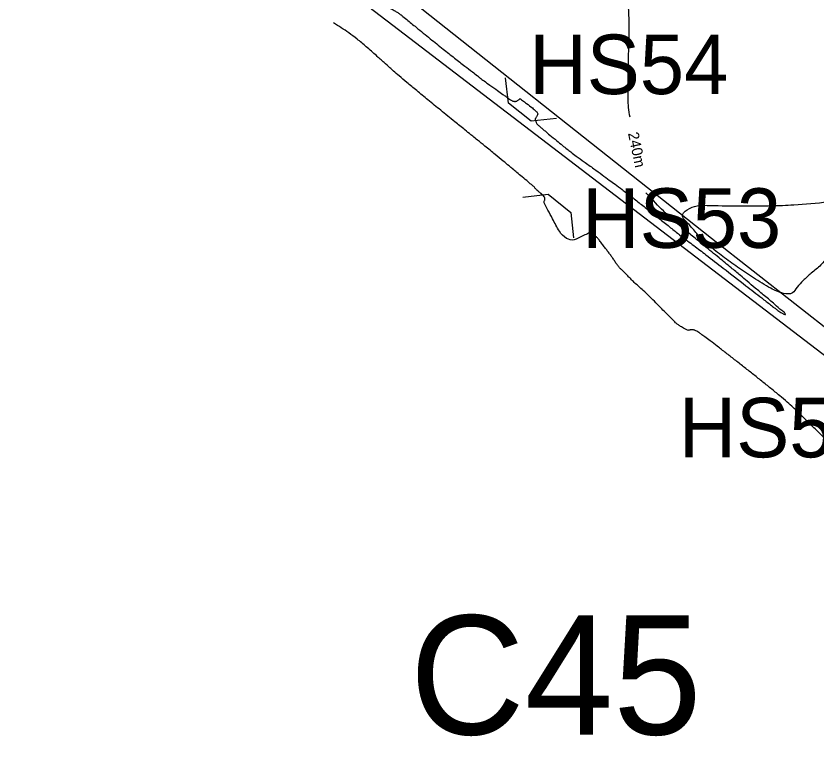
# Model space of a CAD drawing. Extents: x -478495 to -472450, y -1118050 to -1113745.
# Drawn here: x -476976.4 to -476841.8, y -1115248.8 to -1115126.7 of the extents above; entities that cross this region are included whole.
import ezdxf

# ---------------------------------------------------------------- set-up
doc = ezdxf.new("R2010")
doc.units = 0
for name, color, linetype in [('cesty', 7, 'Continuous'), ('cyklostezka', 7, 'Continuous'), ('hospodářské sjezdy', 7, 'Continuous'), ('silnice', 7, 'Continuous'), ('Vrstevnice_hlavni', 7, 'Continuous'), ('Vrstevnice_popis', 7, 'Continuous'), ('Vrstevnice_vedlejsi', 7, 'Continuous')]:
    doc.layers.add(name, color=color, linetype=linetype)

msp = doc.modelspace()

# ---------------------------------------------------------------- linework, layer by layer
at = {"layer": 'cyklostezka'}
msp.add_lwpolyline([(-477033.5754190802, -1115019.3150603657), (-476978.4562666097, -1115069.8432601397), (-476859.56050309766, -1115163.970078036), (-476838.56618741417, -1115180.4272610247), (-476823.49769734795, -1115192.2844335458), (-476742.0352354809, -1115258.9995421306), (-476654.0177406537, -1115335.224940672), (-476615.8651919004, -1115370.6739552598), (-476567.0504242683, -1115426.523456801)], dxfattribs=at)
at = {"layer": 'hospodářské sjezdy'}
for p, q in [((-476893.6856083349, -1115141.2997878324), (-476894.1564470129, -1115137.060401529)), ((-476889.873, -1115144.354), (-476893.6856083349, -1115141.2997878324)), ((-476885.6330406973, -1115143.888349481), (-476889.873, -1115144.354)), ((-476891.2552469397, -1115157.0783249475), (-476887.015287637, -1115156.6126744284)), ((-476887.015287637, -1115156.6126744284), (-476883.2026793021, -1115159.666886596)), ((-476883.2026793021, -1115159.666886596), (-476882.7318406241, -1115163.9062728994))]:
    msp.add_line(p, q, dxfattribs=at)
at = {"layer": 'silnice'}
msp.add_lwpolyline([(-476200.5430969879, -1116268.1533225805), (-476239.9646638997, -1116179.1988064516), (-476260.9335824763, -1116109.5457419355), (-476288.6125549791, -1116007.1641290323), (-476289.4513117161, -1115970.2396129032), (-476274.35369035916, -1115930.797516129), (-476257.5785554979, -1115904.782516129), (-476369.13277385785, -1115816.6670000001), (-476386.7466654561, -1115803.239903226), (-476421.13569191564, -1115718.4813548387), (-476492.4300150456, -1115557.3561935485), (-476531.85169606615, -1115480.150387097), (-476576.30580343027, -1115421.4068387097), (-476632.5025051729, -1115358.4673225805), (-476738.18585476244, -1115266.156032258), (-476821.72644138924, -1115198.097580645), (-476986.4582147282, -1115072.218548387), (-477038.7966192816, -1115021.8669354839), (-477039.4315830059, -1115021.0219319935)], dxfattribs=at)
at = {"layer": 'Vrstevnice_hlavni'}
for points in [[(-476873.251, -1115143.677), (-476873.507, -1115142.01), (-476873.554, -1115139.102), (-476873.522, -1115134.12), (-476873.41000000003, -1115127.063), (-476873.808, -1115122.0860000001), (-476874.717, -1115119.19), (-476876.136, -1115118.374), (-476877.354, -1115117.171), (-476878.371, -1115115.579), (-476879.185, -1115113.6), (-476882.364, -1115111.475), (-476887.908, -1115109.205), (-476895.815, -1115106.789), (-476902.242, -1115103.761), (-476907.186, -1115100.12), (-476910.64900000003, -1115095.867), (-476913.66000000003, -1115091.883), (-476916.218, -1115088.1670000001), (-476918.324, -1115084.72), (-476919.72500000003, -1115082.379), (-476920.42100000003, -1115081.145), (-476920.412, -1115081.017), (-476920.42600000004, -1115080.932), (-476920.462, -1115080.891), (-476920.521, -1115080.893), (-476920.576, -1115080.895), (-476920.62700000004, -1115080.896), (-476920.674, -1115080.898), (-476921.73600000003, -1115080.799), (-476923.814, -1115080.599), (-476926.907, -1115080.3), (-476932.302, -1115079.591), (-476940, -1115078.472), (-476950, -1115076.9440000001), (-476957.876, -1115075.006), (-476963.629, -1115072.6570000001), (-476967.259, -1115069.897), (-476970.802, -1115067.892), (-476974.259, -1115066.643), (-476977.631, -1115066.149), (-476980.601, -1115065.341), (-476983.17, -1115064.218), (-476985.338, -1115062.781), (-476986.878, -1115061.747), (-476987.79000000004, -1115061.118), (-476988.074, -1115060.892), (-476988.478, -1115060.587), (-476989.003, -1115060.204), (-476989.648, -1115059.743), (-476990.332, -1115059.246), (-476991.055, -1115058.714), (-476991.817, -1115058.146), (-476992.891, -1115057.395), (-476994.277, -1115056.46), (-476995.976, -1115055.343), (-476997.039, -1115054.593), (-476997.46400000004, -1115054.21), (-476997.254, -1115054.195), (-476998.009, -1115053.437), (-476999.729, -1115051.937), (-477002.416, -1115049.693), (-477004.444, -1115048.001), (-477005.814, -1115046.86), (-477006.527, -1115046.27), (-477007.324, -1115045.723), (-477008.206, -1115045.2210000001), (-477009.173, -1115044.763), (-477009.833, -1115044.445), (-477010.186, -1115044.267), (-477010.232, -1115044.2280000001), (-477010.318, -1115044.158), (-477010.443, -1115044.058), (-477010.608, -1115043.927), (-477010.86600000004, -1115043.703), (-477011.219, -1115043.389), (-477011.666, -1115042.982), (-477011.859, -1115042.654), (-477011.79600000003, -1115042.405), (-477011.479, -1115042.235), (-477011.695, -1115041.8460000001), (-477012.445, -1115041.236), (-477013.729, -1115040.4070000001), (-477014.642, -1115039.799), (-477015.184, -1115039.41), (-477015.355, -1115039.241), (-477015.476, -1115039.117), (-477015.545, -1115039.038), (-477015.564, -1115039.003), (-477015.672, -1115038.875), (-477015.869, -1115038.653), (-477016.157, -1115038.339), (-477016.405, -1115038.07), (-477016.615, -1115037.849), (-477016.786, -1115037.674), (-477017.213, -1115037.2820000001), (-477017.89400000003, -1115036.673)], [(-476935.331, -1115108.3190000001), (-476934.947, -1115108.607), (-476934.41500000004, -1115109.009), (-476933.73600000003, -1115109.525), (-476932.909, -1115110.156), (-476932.006, -1115110.842), (-476931.026, -1115111.583), (-476929.968, -1115112.379), (-476928.913, -1115113.236), (-476927.86, -1115114.154), (-476926.808, -1115115.132), (-476926.037, -1115115.767), (-476925.54600000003, -1115116.058), (-476925.335, -1115116.006), (-476925.325, -1115115.864), (-476925.515, -1115115.632), (-476925.905, -1115115.311), (-476926.044, -1115115.192), (-476925.931, -1115115.276), (-476925.565, -1115115.563), (-476925.29000000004, -1115115.779), (-476925.105, -1115115.925), (-476925.01, -1115116.002), (-476924.95, -1115116.053), (-476924.925, -1115116.079), (-476924.935, -1115116.079), (-476924.936, -1115116.133), (-476924.927, -1115116.239), (-476924.909, -1115116.398), (-476924.628, -1115116.734), (-476924.083, -1115117.247), (-476923.275, -1115117.937), (-476921.987, -1115119.01), (-476920.22000000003, -1115120.464), (-476917.972, -1115122.302), (-476916.102, -1115123.736), (-476914.608, -1115124.768), (-476913.49, -1115125.397), (-476912.67600000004, -1115125.868), (-476912.164, -1115126.18), (-476911.956, -1115126.335), (-476911.795, -1115126.454), (-476911.684, -1115126.538), (-476911.62, -1115126.587), (-476910.788, -1115127.262), (-476909.18700000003, -1115128.562), (-476906.818, -1115130.4880000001), (-476904.666, -1115132.215), (-476902.733, -1115133.742), (-476901.01900000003, -1115135.07), (-476899.74, -1115136.063), (-476898.897, -1115136.7210000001), (-476898.49, -1115137.044), (-476897.79000000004, -1115137.566), (-476896.79600000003, -1115138.286), (-476895.509, -1115139.205), (-476894.623, -1115139.837), (-476894.139, -1115140.183), (-476894.056, -1115140.242), (-476893.9, -1115140.355), (-476893.67, -1115140.521), (-476893.367, -1115140.74), (-476893.126, -1115140.887), (-476892.94800000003, -1115140.962), (-476892.83400000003, -1115140.965), (-476892.748, -1115140.977), (-476892.691, -1115140.997), (-476892.664, -1115141.027), (-476892.601, -1115141.034), (-476892.501, -1115141.018), (-476892.364, -1115140.98), (-476892.219, -1115140.91), (-476892.065, -1115140.81), (-476891.902, -1115140.679), (-476891.793, -1115140.591), (-476891.738, -1115140.546), (-476891.737, -1115140.543), (-476891.726, -1115140.55), (-476891.70300000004, -1115140.565), (-476891.67100000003, -1115140.589), (-476891.32, -1115140.854), (-476890.651, -1115141.361), (-476889.664, -1115142.109), (-476889.038, -1115142.693), (-476888.773, -1115143.114), (-476888.869, -1115143.371), (-476888.96400000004, -1115143.585), (-476889.059, -1115143.757), (-476889.15400000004, -1115143.887), (-476889.202, -1115143.9980000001), (-476889.202, -1115144.091), (-476889.15400000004, -1115144.166), (-476889.109, -1115144.273), (-476889.066, -1115144.412), (-476889.025, -1115144.583), (-476888.922, -1115144.761), (-476888.756, -1115144.947)], [(-476909.112, -1115139.205), (-476910.765, -1115137.833), (-476912.065, -1115136.734), (-476913.014, -1115135.91), (-476913.61, -1115135.36), (-476914.568, -1115134.496), (-476915.89, -1115133.318), (-476917.57300000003, -1115131.827), (-476919.12, -1115130.555), (-476920.52900000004, -1115129.502), (-476923.072, -1115127.835)], [(-476845.099, -1115193.1300000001), (-476845.83900000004, -1115192.41), (-476846.835, -1115191.519), (-476848.08900000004, -1115190.457), (-476849.601, -1115189.225), (-476851.12, -1115188), (-476852.648, -1115186.783), (-476854.184, -1115185.575), (-476855.685, -1115184.401), (-476857.152, -1115183.259), (-476858.58400000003, -1115182.151), (-476859.759, -1115181.253), (-476860.677, -1115180.563), (-476861.33900000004, -1115180.083), (-476861.843, -1115179.7380000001), (-476862.19, -1115179.528), (-476862.38, -1115179.453), (-476862.58400000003, -1115179.4070000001), (-476862.802, -1115179.3900000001), (-476863.033, -1115179.403), (-476863.218, -1115179.423), (-476863.357, -1115179.45), (-476863.451, -1115179.484), (-476863.713, -1115179.3900000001), (-476864.143, -1115179.1670000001), (-476864.743, -1115178.815), (-476865.227, -1115178.4880000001), (-476865.596, -1115178.186), (-476865.849, -1115177.909), (-476866.126, -1115177.624), (-476866.428, -1115177.33), (-476866.753, -1115177.028), (-476867.316, -1115176.4710000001), (-476868.117, -1115175.659), (-476869.157, -1115174.592), (-476870.123, -1115173.638), (-476871.017, -1115172.797), (-476871.836, -1115172.0690000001), (-476872.543, -1115171.4170000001), (-476873.136, -1115170.84), (-476873.615, -1115170.339), (-476874.055, -1115169.892), (-476874.455, -1115169.501), (-476874.815, -1115169.166), (-476875.17100000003, -1115168.764), (-476875.52400000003, -1115168.297), (-476875.87200000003, -1115167.764), (-476876.23, -1115167.243), (-476876.598, -1115166.734), (-476876.97500000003, -1115166.2380000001), (-476877.38, -1115165.704), (-476877.813, -1115165.134), (-476878.273, -1115164.527), (-476878.668, -1115164.05), (-476878.999, -1115163.702), (-476879.266, -1115163.485), (-476879.494, -1115163.3090000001), (-476879.683, -1115163.175), (-476879.83400000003, -1115163.084), (-476880.378, -1115163.239), (-476881.314, -1115163.642), (-476882.64400000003, -1115164.291), (-476883.912, -1115164.024), (-476885.117, -1115162.84), (-476886.261, -1115160.74), (-476887.06200000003, -1115159.257), (-476887.521, -1115158.391), (-476887.63800000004, -1115158.143), (-476887.685, -1115157.928), (-476887.662, -1115157.746), (-476887.569, -1115157.598), (-476887.54600000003, -1115157.427), (-476887.593, -1115157.234), (-476887.71, -1115157.019), (-476887.916, -1115156.772), (-476888.212, -1115156.494), (-476888.598, -1115156.185), (-476888.896, -1115155.923), (-476889.107, -1115155.707), (-476889.231, -1115155.538), (-476889.651, -1115155.146), (-476890.369, -1115154.53), (-476891.382, -1115153.692), (-476892.256, -1115152.965), (-476892.988, -1115152.35), (-476893.58, -1115151.848), (-476894.552, -1115151.0420000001), (-476895.90400000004, -1115149.9340000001), (-476897.635, -1115148.524), (-476898.89400000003, -1115147.501), (-476899.681, -1115146.865), (-476899.995, -1115146.616), (-476900.999, -1115145.806), (-476902.693, -1115144.437), (-476905.076, -1115142.507), (-476907.216, -1115140.763), (-476909.112, -1115139.205)], [(-476888.756, -1115144.947), (-476888.528, -1115145.142), (-476888.329, -1115145.312), (-476888.161, -1115145.459), (-476888.021, -1115145.583), (-476887.543, -1115145.984), (-476886.726, -1115146.663), (-476885.57, -1115147.618), (-476884.601, -1115148.411), (-476883.82, -1115149.04), (-476883.22500000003, -1115149.506), (-476882.28, -1115150.208), (-476880.987, -1115151.148), (-476879.34500000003, -1115152.325), (-476877.927, -1115153.348), (-476876.732, -1115154.219), (-476875.762, -1115154.936), (-476874.57, -1115155.838), (-476873.157, -1115156.923), (-476871.523, -1115158.193), (-476869.857, -1115159.501), (-476868.159, -1115160.848), (-476866.429, -1115162.234), (-476864.911, -1115163.429), (-476863.604, -1115164.433), (-476862.509, -1115165.247), (-476860.504, -1115166.775), (-476857.591, -1115169.019), (-476853.768, -1115171.979), (-476851.113, -1115174.036), (-476849.625, -1115175.192), (-476849.304, -1115175.446), (-476849.016, -1115175.673), (-476848.76, -1115175.8730000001), (-476848.537, -1115176.046), (-476848.25200000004, -1115176.239), (-476847.906, -1115176.453), (-476847.499, -1115176.687), (-476847.238, -1115176.805), (-476847.12200000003, -1115176.808), (-476847.153, -1115176.6940000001), (-476847.753, -1115176.133), (-476848.923, -1115175.122), (-476850.662, -1115173.663), (-476852.205, -1115172.367), (-476853.55, -1115171.235), (-476854.69800000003, -1115170.266), (-476856.278, -1115168.952), (-476858.291, -1115167.291), (-476860.737, -1115165.284), (-476862.754, -1115163.633), (-476864.343, -1115162.339), (-476865.503, -1115161.4), (-476866.711, -1115160.318), (-476867.965, -1115159.093), (-476870.569, -1115156.356)], [(-476839.999, -1115157.895), (-476845.73, -1115158.387), (-476849.518, -1115158.527), (-476854.229, -1115158.56), (-476859.862, -1115158.486), (-476863.257, -1115158.987), (-476864.412, -1115160.064), (-476863.32800000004, -1115161.717), (-476861.842, -1115163.433), (-476859.954, -1115165.214), (-476857.664, -1115167.058), (-476855.178, -1115168.872), (-476852.495, -1115170.6570000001), (-476849.61600000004, -1115172.412), (-476847.438, -1115173.258), (-476845.963, -1115173.1940000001), (-476845.189, -1115172.22), (-476844.134, -1115171.11), (-476842.79600000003, -1115169.8630000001), (-476841.17600000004, -1115168.481), (-476839.95, -1115166.85), (-476839.117, -1115164.9710000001), (-476838.678, -1115162.845), (-476838.445, -1115161.3260000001), (-476838.419, -1115160.414), (-476838.60000000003, -1115160.11), (-476838.856, -1115159.695), (-476839.18700000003, -1115159.169), (-476839.999, -1115157.895)], [(-476855.569, -1115256.142), (-476855.115, -1115256.093), (-476854.291, -1115255.936), (-476852.87, -1115255.649), (-476850.852, -1115255.229), (-476848.677, -1115255.084), (-476846.34500000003, -1115255.212), (-476843.857, -1115255.614), (-476841.272, -1115256.427), (-476838.58900000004, -1115257.651), (-476835.81, -1115259.286), (-476833.757, -1115260.487), (-476832.43, -1115261.254), (-476831.82800000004, -1115261.587), (-476830.897, -1115262.173), (-476829.636, -1115263.01), (-476828.04600000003, -1115264.1), (-476826.65400000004, -1115264.9980000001), (-476825.458, -1115265.704), (-476824.46, -1115266.218), (-476823.452, -1115266.302), (-476822.434, -1115265.959), (-476821.406, -1115265.186), (-476820.43200000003, -1115264.893), (-476819.512, -1115265.08), (-476818.647, -1115265.746), (-476818.193, -1115265.682), (-476818.151, -1115264.889), (-476818.522, -1115263.366), (-476818.174, -1115260.752), (-476817.109, -1115257.048), (-476815.327, -1115252.252), (-476813.909, -1115248.046), (-476812.856, -1115244.431), (-476812.168, -1115241.405), (-476812.01, -1115238.78), (-476812.38300000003, -1115236.557), (-476813.287, -1115234.735), (-476814.205, -1115233.315), (-476815.13800000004, -1115232.298), (-476816.085, -1115231.6840000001), (-476816.776, -1115231.22), (-476817.211, -1115230.908), (-476817.39, -1115230.746), (-476817.237, -1115230.458), (-476816.75200000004, -1115230.045), (-476815.934, -1115229.506), (-476815.287, -1115229.08), (-476814.811, -1115228.769), (-476814.505, -1115228.571), (-476813.847, -1115228.099), (-476812.837, -1115227.352), (-476811.47500000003, -1115226.332), (-476810.826, -1115225.65), (-476810.891, -1115225.305), (-476811.67, -1115225.299), (-476812.342, -1115225.139), (-476812.908, -1115224.8260000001), (-476813.367, -1115224.359), (-476813.789, -1115223.676), (-476814.174, -1115222.777), (-476814.522, -1115221.662), (-476814.87700000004, -1115220.642), (-476815.24, -1115219.718), (-476815.609, -1115218.8900000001), (-476815.995, -1115218.223), (-476816.397, -1115217.715), (-476816.816, -1115217.368), (-476817.142, -1115217.097), (-476817.373, -1115216.903), (-476817.511, -1115216.785), (-476818.01900000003, -1115216.345), (-476818.895, -1115215.585), (-476820.14, -1115214.503), (-476821.561, -1115213.352), (-476823.157, -1115212.134), (-476824.929, -1115210.847), (-476826.146, -1115209.959), (-476826.808, -1115209.468), (-476826.916, -1115209.375), (-476827.362, -1115208.989), (-476828.147, -1115208.31), (-476829.27, -1115207.337), (-476830.76, -1115206.092), (-476832.617, -1115204.573), (-476834.841, -1115202.7820000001), (-476836.397, -1115201.53), (-476837.287, -1115200.818), (-476837.51, -1115200.645), (-476837.66000000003, -1115200.526), (-476837.737, -1115200.46), (-476837.742, -1115200.448), (-476838.481, -1115199.708), (-476839.952, -1115198.24), (-476842.156, -1115196.045), (-476843.87200000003, -1115194.341), (-476845.099, -1115193.1300000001)]]:
    msp.add_spline(points, degree=3, dxfattribs=at)
at = {"layer": 'Vrstevnice_vedlejsi'}
for points in [[(-476865.118, -1114947.811), (-476865.909, -1114953.905), (-476866.397, -1114959.485), (-476866.583, -1114964.551), (-476866.466, -1114969.101), (-476866.298, -1114975.062), (-476866.079, -1114982.4340000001), (-476865.81, -1114991.217), (-476862.793, -1115001.5), (-476857.028, -1115013.281), (-476848.514, -1115026.563), (-476842.83, -1115035.427), (-476839.976, -1115039.872), (-476839.952, -1115039.9), (-476839.93200000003, -1115039.927), (-476839.916, -1115039.952), (-476839.90400000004, -1115039.976), (-476839.84500000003, -1115040.056), (-476839.73600000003, -1115040.192), (-476839.58, -1115040.384), (-476835.718, -1115044.893), (-476828.15, -1115053.719), (-476816.875, -1115066.861), (-476808.737, -1115076.31), (-476803.734, -1115082.065), (-476801.867, -1115084.127), (-476797.75200000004, -1115089.088), (-476791.389, -1115096.949), (-476782.77900000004, -1115107.71), (-476776.767, -1115115.206), (-476773.353, -1115119.437), (-476772.537, -1115120.403), (-476772.031, -1115121.162), (-476771.83400000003, -1115121.714), (-476771.946, -1115122.0590000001), (-476771.93700000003, -1115122.445), (-476771.806, -1115122.872), (-476771.554, -1115123.34), (-476770.597, -1115124.4980000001), (-476768.934, -1115126.3460000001), (-476766.566, -1115128.885), (-476764.193, -1115131.746), (-476761.815, -1115134.93), (-476759.431, -1115138.437), (-476757.58900000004, -1115140.867), (-476756.286, -1115142.2210000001), (-476755.52400000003, -1115142.497), (-476754.929, -1115142.712), (-476754.5, -1115142.865), (-476754.239, -1115142.958), (-476753.581, -1115143.571), (-476752.527, -1115144.705), (-476751.076, -1115146.36), (-476749.018, -1115148.796), (-476746.353, -1115152.01), (-476743.082, -1115156.0050000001), (-476739.879, -1115159.848), (-476736.745, -1115163.538), (-476733.68, -1115167.0760000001), (-476730.457, -1115172.213), (-476727.076, -1115178.95), (-476723.538, -1115187.285), (-476720.898, -1115193.299), (-476719.156, -1115196.992), (-476718.31200000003, -1115198.364), (-476716.879, -1115200.043), (-476714.858, -1115202.028), (-476712.249, -1115204.321), (-476710.783, -1115206.301), (-476710.45900000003, -1115207.9710000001), (-476711.277, -1115209.329), (-476711.851, -1115210.263), (-476712.181, -1115210.774), (-476712.265, -1115210.862), (-476712.362, -1115210.9980000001), (-476712.472, -1115211.183), (-476712.594, -1115211.4170000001), (-476712.099, -1115212.259), (-476710.98600000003, -1115213.71), (-476709.256, -1115215.769), (-476706.933, -1115218.347), (-476704.018, -1115221.445), (-476700.511, -1115225.062), (-476697.57283116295, -1115227.8820723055)], [(-476757.389, -1115194.577), (-476758.695, -1115193.071), (-476762.715, -1115189.575), (-476769.45, -1115184.09), (-476778.9, -1115176.617), (-476785.233, -1115171.626), (-476788.449, -1115169.12), (-476788.548, -1115169.097), (-476788.61600000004, -1115169.0690000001), (-476788.652, -1115169.036), (-476788.658, -1115168.9980000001), (-476788.97500000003, -1115168.981), (-476789.604, -1115168.985), (-476790.544, -1115169.009), (-476791.34, -1115169.0690000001), (-476791.993, -1115169.163), (-476792.50200000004, -1115169.2920000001), (-476792.841, -1115169.3530000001), (-476793.01, -1115169.345), (-476793.00800000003, -1115169.27), (-476793.01, -1115169.218), (-476793.016, -1115169.19), (-476793.02400000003, -1115169.185), (-476793.11600000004, -1115169.12), (-476793.292, -1115168.995), (-476793.55, -1115168.808), (-476794.162, -1115168.339), (-476795.126, -1115167.587), (-476796.444, -1115166.554), (-476797.585, -1115165.656), (-476798.549, -1115164.894), (-476799.337, -1115164.267), (-476799.874, -1115163.8360000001), (-476800.159, -1115163.599), (-476800.193, -1115163.557), (-476800.227, -1115163.476), (-476800.26, -1115163.355), (-476800.292, -1115163.1940000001), (-476800.74, -1115161.892), (-476801.603, -1115159.447), (-476802.88300000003, -1115155.861), (-476803.7, -1115153.354), (-476804.054, -1115151.925), (-476803.945, -1115151.575), (-476804.007, -1115151.177), (-476804.24, -1115150.731), (-476804.64400000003, -1115150.237), (-476804.919, -1115149.909), (-476805.064, -1115149.746), (-476805.079, -1115149.749), (-476805.08900000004, -1115149.743), (-476805.092, -1115149.729), (-476805.09, -1115149.708), (-476805.189, -1115149.233), (-476805.389, -1115148.305), (-476805.689, -1115146.924), (-476806.577, -1115144.876), (-476808.05100000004, -1115142.162), (-476810.112, -1115138.7820000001), (-476812.7, -1115134.82), (-476815.815, -1115130.275), (-476819.457, -1115125.148), (-476823.762, -1115119.561), (-476828.729, -1115113.513), (-476834.358, -1115107.004), (-476839.556, -1115101.834), (-476844.32300000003, -1115098.003), (-476848.659, -1115095.511), (-476852.145, -1115092.404), (-476854.77900000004, -1115088.6840000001), (-476856.564, -1115084.349), (-476859.10000000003, -1115080.398), (-476862.389, -1115076.832), (-476866.429, -1115073.651), (-476870.181, -1115070.045), (-476873.646, -1115066.014), (-476876.82300000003, -1115061.5590000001), (-476880.36600000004, -1115058.1130000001), (-476884.273, -1115055.676), (-476888.547, -1115054.2480000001), (-476892.21, -1115051.872), (-476895.264, -1115048.547), (-476897.708, -1115044.273), (-476900.496, -1115040.378), (-476903.629, -1115036.861), (-476907.106, -1115033.723), (-476910.359, -1115028.232), (-476913.387, -1115020.389), (-476916.191, -1115010.195), (-476918.00800000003, -1115003.154), (-476918.83900000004, -1114999.267), (-476918.684, -1114998.534), (-476918.744, -1114997.862), (-476919.01900000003, -1114997.249), (-476919.51, -1114996.697), (-476920.516, -1114995.4340000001), (-476922.039, -1114993.459)]]:
    msp.add_spline(points, degree=3, dxfattribs=at)

# ---------------------------------------------------------------- texts
at = {"layer": 'cesty'}
msp.add_text('C45', height=19.999999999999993, rotation=359.99999385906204, dxfattribs=at).set_placement((-476910.27396586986, -1115247.366106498))
at = {"layer": 'hospodářské sjezdy'}
for s, p in [('HS54', (-476890.18355831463, -1115139.7898796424)), ('HS53', (-476881.29617959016, -1115165.6169915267)), ('HS52', (-476865.07087505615, -1115200.8092942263))]:
    msp.add_text(s, height=9.999999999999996, rotation=359.99999385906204, dxfattribs=at).set_placement(p)
at = {"layer": 'Vrstevnice_popis'}
msp.add_text(' 240m ', height=1.7999999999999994, rotation=281.8768244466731, dxfattribs=at).set_placement((-476873.745, -1115145.712))

doc.saveas('drawing.dxf')
